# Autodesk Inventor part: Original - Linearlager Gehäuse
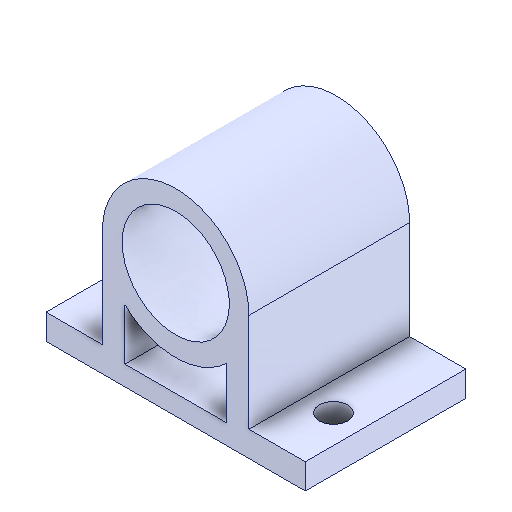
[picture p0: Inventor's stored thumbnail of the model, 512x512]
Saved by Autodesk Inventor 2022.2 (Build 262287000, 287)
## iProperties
Created: 2024-09
Part Number: Original - Linearlager Gehäuse
Material: Generico
Document SubType Name: Modeling
Designer: 18907419
Density: 1 g/cm^3
Appearance: Default
Author: 18907419
Revision Number: ANY
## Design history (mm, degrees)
feature "Schnitt-Linear austragen1"
node "Solido1"
